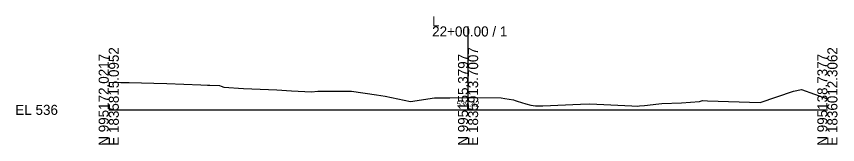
# Model space of a CAD drawing. Extents: x -26 to 2403, y -10 to 9558.
# Drawn here: x 2174.3 to 2402.8, y 2490.3 to 2526.1 of the extents above; entities that cross this region are included whole.
import ezdxf

# ---------------------------------------------------------------- set-up
doc = ezdxf.new("R2010")
doc.units = 0
for name, color, linetype in [('Exist CMT Ground Line', 7, 'Continuous'), ('Exist Cross Section Cell', 7, 'Continuous'), ('Exist XS Center Line Elevation Label', 7, 'Continuous')]:
    doc.layers.add(name, color=color, linetype=linetype)

msp = doc.modelspace()

# ---------------------------------------------------------------- linework, layer by layer
at = {"layer": 'Exist CMT Ground Line'}
for p, q in [((2200, 2507.76), (2203.38, 2507.65)), ((2203.38, 2507.65), (2205.71, 2507.59)), ((2205.71, 2507.59), (2212.55, 2507.46)), ((2212.55, 2507.46), (2216.15, 2507.36)), ((2216.15, 2507.36), (2225.64, 2506.96)), ((2225.64, 2506.96), (2227.49, 2506.91)), ((2227.49, 2506.91), (2228.16, 2506.92)), ((2228.16, 2506.92), (2230.82, 2506.79)), ((2230.82, 2506.79), (2231.31, 2506.62)), ((2231.31, 2506.62), (2232.03, 2506.33)), ((2232.03, 2506.33), (2237.52, 2505.93)), ((2237.52, 2505.93), (2246.75, 2505.54)), ((2246.75, 2505.54), (2250.88, 2505.28)), ((2250.88, 2505.28), (2256.41, 2504.98)), ((2256.41, 2504.98), (2258.18, 2505.18)), ((2258.18, 2505.18), (2260.96, 2505.23)), ((2260.96, 2505.23), (2267.58, 2505.21)), ((2267.58, 2505.21), (2274.54, 2504.16)), ((2381.3, 2502.03), (2390.55, 2505.23)), ((2390.55, 2505.23), (2392.82, 2505.7)), ((2392.82, 2505.7), (2400, 2503.03)), ((2274.54, 2504.16), (2276.92, 2503.86)), ((2276.92, 2503.86), (2283.97, 2502.37)), ((2283.97, 2502.37), (2290.64, 2503.35)), ((2290.64, 2503.35), (2294.92, 2503.38)), ((2294.92, 2503.38), (2299.88, 2503.42)), ((2299.88, 2503.42), (2302.01, 2503.41)), ((2302.01, 2503.41), (2309.17, 2503.35)), ((2309.17, 2503.35), (2310.27, 2503.18)), ((2310.27, 2503.18), (2312.61, 2502.81)), ((2312.61, 2502.81), (2313.13, 2502.62)), ((2313.13, 2502.62), (2313.69, 2502.44)), ((2313.69, 2502.44), (2316.08, 2501.69)), ((2364.45, 2502.37), (2365.23, 2502.58)), ((2365.23, 2502.58), (2366.65, 2502.49)), ((2366.65, 2502.49), (2381.3, 2502.03)), ((2316.08, 2501.69), (2317.45, 2501.34)), ((2317.45, 2501.34), (2318.77, 2501.09)), ((2318.77, 2501.09), (2320.83, 2501.14)), ((2320.83, 2501.14), (2331.29, 2501.56)), ((2331.29, 2501.56), (2333.91, 2501.68)), ((2333.91, 2501.68), (2345.55, 2501.14)), ((2345.55, 2501.14), (2347.26, 2501.07)), ((2347.26, 2501.07), (2347.74, 2501.08)), ((2347.74, 2501.08), (2349.11, 2501.24)), ((2349.11, 2501.24), (2353.1, 2501.68)), ((2353.1, 2501.68), (2353.93, 2501.77)), ((2353.93, 2501.77), (2359.42, 2501.92)), ((2359.42, 2501.92), (2364.45, 2502.37))]:
    msp.add_line(p, q, dxfattribs=at)
at = {"layer": 'Exist Cross Section Cell'}
for p, q in [((2300, 2500), (2300, 2523.27)), ((2200, 2500), (2300, 2500)), ((2300, 2500), (2400, 2500))]:
    msp.add_line(p, q, dxfattribs=at)

# ---------------------------------------------------------------- texts
for s, p in [('L', (2290, 2523.27)), ('22+00.00 / 1', (2290, 2520.47)), ('EL 536', (2174, 2498.6))]:
    msp.add_text(s, height=2.8, dxfattribs=at).set_placement(p)
for s, p in [('E 1835815.0952', (2202.8, 2490)), ('E 1835913.7007', (2302.8, 2490)), ('E 1836012.3062', (2402.8, 2490)), ('N 995172.0217', (2200, 2490)), ('N 995155.3797', (2300, 2490)), ('N 995138.7377', (2400, 2490))]:
    msp.add_text(s, height=2.8, rotation=90, dxfattribs=at).set_placement(p)
at = {"layer": 'Exist XS Center Line Elevation Label'}
msp.add_text('539.42', height=1.5, dxfattribs=at).set_placement((2296.84, 2500.92))

doc.saveas('drawing.dxf')
